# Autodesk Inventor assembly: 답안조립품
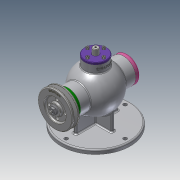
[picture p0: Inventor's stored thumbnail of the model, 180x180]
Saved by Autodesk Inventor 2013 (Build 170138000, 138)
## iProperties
Created: 2020-08
Part Number: 답안조립품
Document SubType Name: Assembly
Designer: 19
Author: 19
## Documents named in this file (18)
- C:\Users\user\Desktop\700806V1011\답안조립품.iam
- C:\Users\user\Desktop\700806V1011\본체.ipt
- C:\Users\user\Desktop\700806V1011\Ű 3x3x12.ipt
- C:\Users\user\Desktop\700806V1011\V-벨트풀리.ipt
- C:\Users\user\Desktop\700806V1011\너트 M8.ipt
- C:\Users\user\Desktop\700806V1011\뒤커버.ipt
- C:\Users\user\Desktop\700806V1011\멈춤링 15x1.ipt
- C:\Users\user\Desktop\700806V1011\멈춤링 35x1.6.ipt
- 멈춤링 35x1.6.ipt
- C:\Users\user\Desktop\700806V1011\베어링 6202.ipt
- 베어링 6202.ipt
- C:\Users\user\Desktop\700806V1011\볼트 M4.ipt
- C:\Users\user\Desktop\700806V1011\상부커버.ipt
- C:\Users\user\Desktop\700806V1011\슬라이드.ipt
- C:\Users\user\Desktop\700806V1011\앞커버.ipt
- C:\Users\user\Desktop\700806V1011\오일 실 15 30 7.ipt
- C:\Users\user\Desktop\700806V1011\칼라.ipt
- C:\Users\user\Desktop\700806V1011\편심축.ipt
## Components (2 placed, 2 different names)
1. Ű 3x3x12:1
2. V-벨트풀리:1
